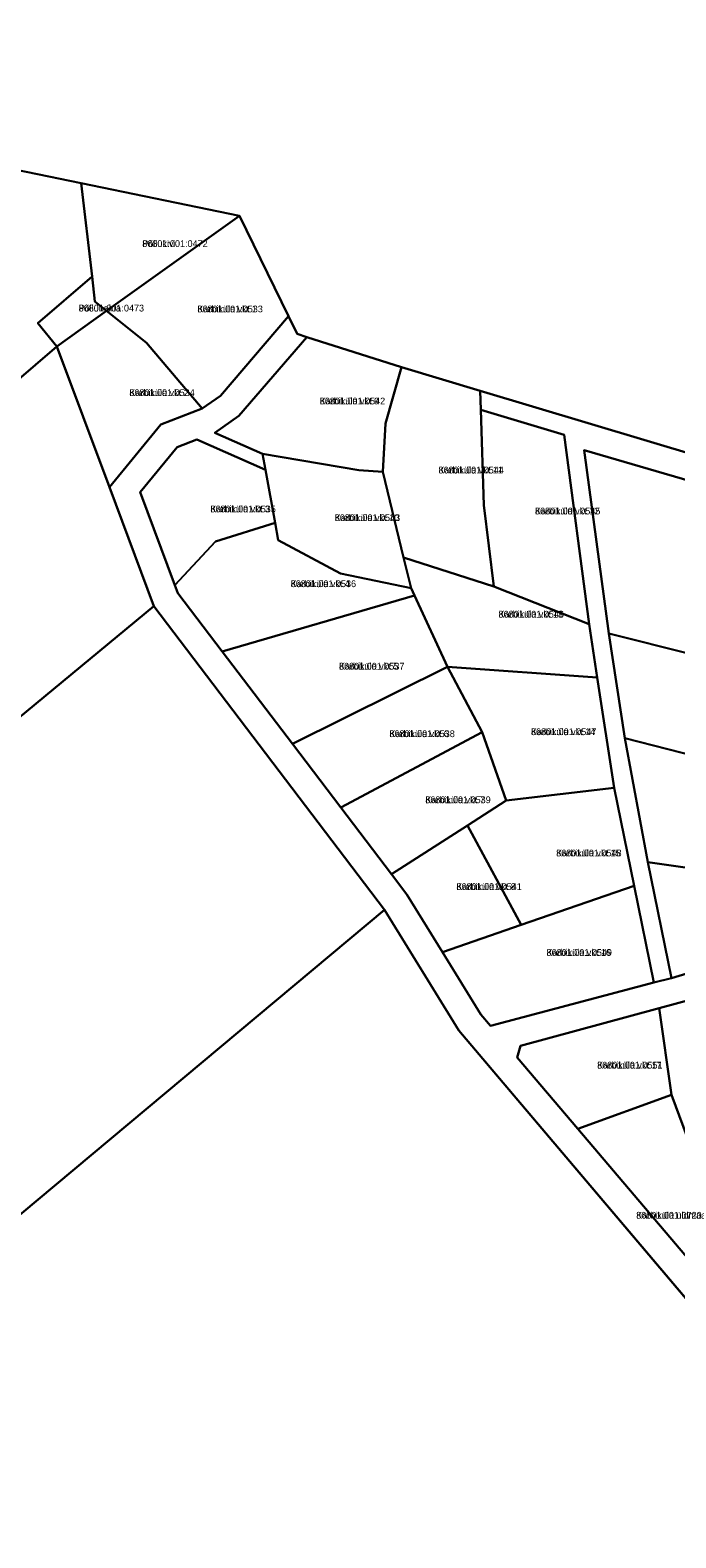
# Model space of a CAD drawing. Extents: x 484607 to 525396, y 6554521 to 6586559.
# Drawn here: x 516796.7 to 516939.9, y 6565291.3 to 6565625.8 of the extents above; entities that cross this region are included whole.
import ezdxf

# ---------------------------------------------------------------- set-up
doc = ezdxf.new("R2010")
doc.units = 0
for name, color, linetype in [('L_AADRESS', 7, 'Continuous'), ('PIIR', 7, 'Continuous'), ('TUNNUS', 7, 'Continuous')]:
    doc.layers.add(name, color=color, linetype=linetype)

msp = doc.modelspace()

# ---------------------------------------------------------------- linework, layer by layer
at = {"layer": 'PIIR'}
for points in [[(516624.51, 6565632.46), (516863.4, 6566170.69), (516868.78, 6566168.5), (516873.7, 6566179.49), (516891.5, 6566178.94), (517065.3, 6565905.83), (517021.69, 6565903.89), (516970.83, 6565902.01), (516969.2, 6565622.68), (516969.03, 6565583.85), (516945.1, 6565531.21), (516896.5, 6565545.83), (516879.03, 6565551.05), (516858.06, 6565557.72), (516855.91, 6565558.43), (516854.01, 6565562.38), (516843.12, 6565584.59), (516808.02, 6565591.89), (516759.59, 6565601.86), (516722.22, 6565619.19), (516611.88, 6565605.35)], [(516611.88, 6565605.35), (516722.22, 6565619.19), (516759.59, 6565601.86), (516808.02, 6565591.89), (516810.46, 6565571.15), (516798.47, 6565560.78), (516802.62, 6565555.66), (516736.34, 6565498.68), (516591.9, 6565559.36)], [(516808.02, 6565591.89), (516843.12, 6565584.59), (516813.64, 6565563.53), (516811.05, 6565565.62), (516810.46, 6565571.15)], [(516843.12, 6565584.59), (516854.01, 6565562.38), (516838.93, 6565544.7), (516834.85, 6565541.84), (516822.53, 6565556.41), (516813.64, 6565563.53)], [(516810.46, 6565571.15), (516811.05, 6565565.62), (516813.64, 6565563.53), (516802.62, 6565555.66), (516798.47, 6565560.78)], [(516813.64, 6565563.53), (516822.53, 6565556.41), (516834.85, 6565541.84), (516825.71, 6565538.36), (516814.3, 6565524.4), (516802.62, 6565555.66)], [(516858.06, 6565557.72), (516879.03, 6565551.05), (516875.49, 6565538.51), (516874.93, 6565527.84), (516869.63, 6565528.21), (516848.26, 6565531.81), (516837.68, 6565536.49), (516842.99, 6565540.22)], [(516802.62, 6565555.66), (516814.3, 6565524.4), (516824.17, 6565497.99), (516472.49, 6565206.92), (516457.33, 6565258.07), (516736.34, 6565498.68)], [(516879.03, 6565551.05), (516896.5, 6565545.83), (516896.67, 6565541.57), (516897.28, 6565520.4), (516899.56, 6565502.4), (516879.53, 6565508.78), (516874.93, 6565527.84), (516875.49, 6565538.51)], [(516896.67, 6565541.57), (516915.1, 6565536.03), (516920.63, 6565494.01), (516899.56, 6565502.4), (516897.28, 6565520.4)], [(516833.69, 6565534.98), (516848.9, 6565528.24), (516851.02, 6565516.52), (516837.86, 6565512.33), (516828.82, 6565502.68), (516821.13, 6565523.28), (516829.34, 6565533.32)], [(516869.63, 6565528.21), (516874.93, 6565527.84), (516879.53, 6565508.78), (516881.17, 6565501.99), (516865.56, 6565505.29), (516851.73, 6565512.63), (516851.02, 6565516.52), (516848.9, 6565528.24), (516848.26, 6565531.81)], [(516919.58, 6565532.61), (516957.33, 6565521.63), (516961.85, 6565482.69), (516925, 6565491.96)], [(516851.02, 6565516.52), (516851.73, 6565512.63), (516865.56, 6565505.29), (516881.17, 6565501.99), (516881.91, 6565500.41), (516839.32, 6565487.96), (516829.48, 6565500.92), (516828.82, 6565502.68), (516837.86, 6565512.33)], [(516879.53, 6565508.78), (516899.56, 6565502.4), (516920.63, 6565494.01), (516922.46, 6565482.18), (516889.29, 6565484.56), (516881.91, 6565500.41), (516881.17, 6565501.99)], [(516881.91, 6565500.41), (516889.29, 6565484.56), (516854.89, 6565467.47), (516839.32, 6565487.96)], [(516824.17, 6565497.99), (516875.31, 6565430.66), (516499.43, 6565116.04), (516472.49, 6565206.92)], [(516925, 6565491.96), (516961.85, 6565482.69), (516963.09, 6565477.72), (516967.39, 6565460.43), (516966.72, 6565458.96), (516928.57, 6565468.76)], [(516889.29, 6565484.56), (516896.93, 6565470.07), (516865.6, 6565453.37), (516854.89, 6565467.47)], [(516889.29, 6565484.56), (516922.46, 6565482.18), (516926.23, 6565457.71), (516902.3, 6565454.92), (516896.93, 6565470.07)], [(516896.93, 6565470.07), (516902.3, 6565454.92), (516893.68, 6565449.36), (516876.87, 6565438.53), (516865.6, 6565453.37)], [(516928.57, 6565468.76), (516966.72, 6565458.96), (516968.68, 6565433.45), (516957.9, 6565437.71), (516933.66, 6565441.24)], [(516902.3, 6565454.92), (516926.23, 6565457.71), (516930.65, 6565435.96), (516905.59, 6565427.27), (516893.68, 6565449.36)], [(516893.68, 6565449.36), (516905.59, 6565427.27), (516888.14, 6565421.23), (516880.27, 6565434.05), (516876.87, 6565438.53)], [(516933.66, 6565441.24), (516957.9, 6565437.71), (516968.68, 6565433.45), (516971.63, 6565427.56), (516961.28, 6565422.26), (516938.89, 6565415.48)], [(516888.14, 6565421.23), (516905.59, 6565427.27), (516930.65, 6565435.96), (516935.01, 6565414.49), (516898.78, 6565404.87), (516896.65, 6565407.38)], [(516875.31, 6565430.66), (516891.78, 6565403.85), (516957.63, 6565326.08), (516977.18, 6565327.34), (517026.74, 6565221.86), (516558.37, 6564917.18), (516499.43, 6565116.04)], [(516936.15, 6565408.79), (516951.18, 6565412.89), (516959.69, 6565385.16), (516954.35, 6565382.79), (516943.25, 6565377.84), (516938.95, 6565389.56)], [(516936.15, 6565408.79), (516938.95, 6565389.56), (516918.13, 6565382.06), (516904.7, 6565397.88), (516905.47, 6565400.43)], [(516938.95, 6565389.56), (516943.25, 6565377.84), (516954.35, 6565382.79), (516956.38, 6565378.41), (516966.26, 6565357.06), (516947.72, 6565347.21), (516918.13, 6565382.06)]]:
    msp.add_lwpolyline(points, close=True, dxfattribs=at)
for points in [[(516942.21, 6565344.28), (516891.78, 6565403.85), (516875.31, 6565430.66), (516824.17, 6565497.99), (516814.3, 6565524.4), (516825.71, 6565538.36), (516834.85, 6565541.84), (516838.93, 6565544.7), (516854.01, 6565562.38), (516855.91, 6565558.43), (516858.06, 6565557.72), (516842.99, 6565540.22), (516837.68, 6565536.49), (516848.26, 6565531.81), (516848.9, 6565528.24), (516833.69, 6565534.98), (516829.34, 6565533.32), (516821.13, 6565523.28), (516828.82, 6565502.68), (516829.48, 6565500.92), (516839.32, 6565487.96), (516854.89, 6565467.47), (516865.6, 6565453.37), (516876.87, 6565438.53), (516880.27, 6565434.05), (516888.14, 6565421.23), (516896.65, 6565407.38), (516898.78, 6565404.87), (516935.01, 6565414.49), (516938.89, 6565415.48), (516961.28, 6565422.26)], [(516957.33, 6565521.63), (516919.58, 6565532.61), (516925, 6565491.96), (516928.57, 6565468.76), (516933.66, 6565441.24), (516938.89, 6565415.48), (516935.01, 6565414.49), (516930.65, 6565435.96), (516926.23, 6565457.71), (516922.46, 6565482.18), (516920.63, 6565494.01), (516915.1, 6565536.03), (516896.67, 6565541.57), (516896.5, 6565545.83), (516945.1, 6565531.21)], [(516951.18, 6565412.89), (516936.15, 6565408.79), (516905.47, 6565400.43), (516904.7, 6565397.88), (516918.13, 6565382.06), (516947.72, 6565347.21)]]:
    msp.add_lwpolyline(points, dxfattribs=at)

# ---------------------------------------------------------------- texts
at = {"layer": 'L_AADRESS'}
for s, p in [('Põllukivi', (516821.59, 6565577.71)), ('Põlluheina', (516807.49, 6565563.4)), ('Karbiküla vkt 1', (516833.82, 6565563.21)), ('Karbiküla vkt 2', (516818.73, 6565544.64)), ('Karbiküla vkt 9', (516860.94, 6565542.78)), ('Karbiküla vkt 11', (516887.25, 6565527.46)), ('Karbiküla vkt 3', (516836.7, 6565518.83)), ('Karbiküla vkt 12', (516908.65, 6565518.37)), ('Karbiküla vkt 10', (516864.26, 6565516.9)), ('Karbiküla vkt 4', (516854.49, 6565502.24)), ('Karbiküla vkt 13', (516900.57, 6565495.48)), ('Karbiküla vkt 5', (516865.21, 6565483.94)), ('Karbiküla vkt 6', (516876.38, 6565468.96)), ('Karbiküla vkt 14', (516907.76, 6565469.4)), ('Karbiküla vkt 7', (516884.34, 6565454.3)), ('Karbiküla vkt 15', (516913.35, 6565442.49)), ('Karbiküla vkt 8', (516891.23, 6565435.04)), ('Karbiküla vkt 16', (516911.22, 6565420.42)), ('Karbiküla vkt 17', (516922.44, 6565395.42)), ('Karbiküla üldmaa 1', (516931.09, 6565362.11))]:
    msp.add_text(s, height=1.5, dxfattribs=at).set_placement(p)
at = {"layer": 'TUNNUS'}
for s, p in [('86801:001:0472', (516821.59, 6565577.71)), ('86801:001:0473', (516807.49, 6565563.4)), ('86801:001:0533', (516833.82, 6565563.21)), ('86801:001:0534', (516818.73, 6565544.64)), ('86801:001:0542', (516860.94, 6565542.78)), ('86801:001:0544', (516887.25, 6565527.46)), ('86801:001:0535', (516836.7, 6565518.83)), ('86801:001:0545', (516908.65, 6565518.37)), ('86801:001:0543', (516864.26, 6565516.9)), ('86801:001:0536', (516854.49, 6565502.24)), ('86801:001:0546', (516900.57, 6565495.48)), ('86801:001:0537', (516865.21, 6565483.94)), ('86801:001:0538', (516876.38, 6565468.96)), ('86801:001:0547', (516907.76, 6565469.4)), ('86801:001:0539', (516884.34, 6565454.3)), ('86801:001:0548', (516913.35, 6565442.49)), ('86801:001:0541', (516891.23, 6565435.04)), ('86801:001:0549', (516911.22, 6565420.42)), ('86801:001:0551', (516922.44, 6565395.42)), ('86801:001:0720', (516931.09, 6565362.11))]:
    msp.add_text(s, height=1.5, dxfattribs=at).set_placement(p)

doc.saveas('drawing.dxf')
